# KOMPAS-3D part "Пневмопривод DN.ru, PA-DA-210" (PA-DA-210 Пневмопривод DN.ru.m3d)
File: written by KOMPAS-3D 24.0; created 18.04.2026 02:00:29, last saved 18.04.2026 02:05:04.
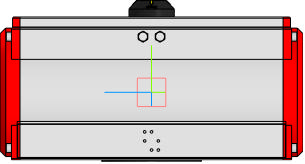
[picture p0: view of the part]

Document properties: Автор: DN.ru; Полное имя файла: C:\Работа\PA-DA-х Пневмопривод DN.ru\210\PA-DA-210 Пневмопривод DN.ru.m3d

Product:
- Part/product: Пневмопривод DN.ru  | designation PA-DA-210
    Масса: 47
    Раздел спецификации: Прочие изделия
    Примечание: D290-00300

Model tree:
1. Операция без истории:1

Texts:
  PA-DA-210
